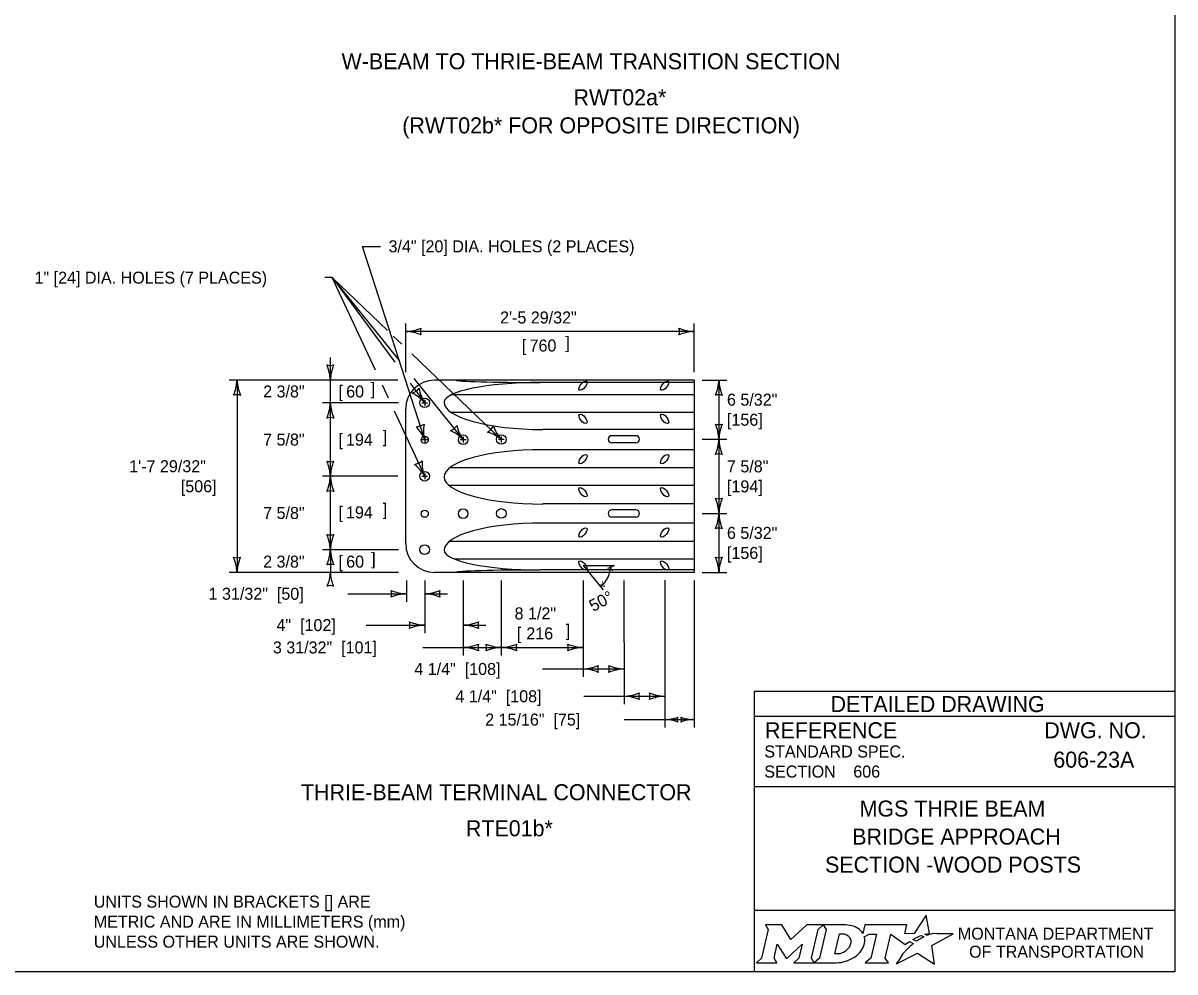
# Model space of a CAD drawing. Extents: x 49991 to 50160, y 49948 to 50051.
# Drawn here: x 50011 to 50016.75, y 49987.8 to 49992.54 of the extents above; entities that cross this region are included whole.
import ezdxf

# ---------------------------------------------------------------- set-up
doc = ezdxf.new("R2010")
doc.units = 0
for name, color, linetype in [('Default', 7, 'Continuous'), ('Level 1', 7, 'Continuous'), ('Level 10', 7, 'Continuous'), ('Level 2', 7, 'Continuous'), ('Level 3', 7, 'Continuous'), ('Level 5', 7, 'Continuous')]:
    doc.layers.add(name, color=color, linetype=linetype)

# ---------------------------------------------------------------- blocks, each defined once
blk = doc.blocks.new('ARRP')
at = {"layer": 'Level 10'}
for centre, major_axis, start_param, end_param in [((0.018, 0.564), (0, -0.565), 5.889718, 6.241987), ((-0.253, 0), (0, -0.139), 1.25906, 1.882533), ((0.023, -0.591), (0, 0.592), 0.049346, 0.385319)]:
    blk.add_ellipse(centre, major_axis=major_axis, ratio=0.77736, start_param=start_param, end_param=end_param, dxfattribs=at)
blk = doc.blocks.new('ARW')
at = {"layer": 'Default'}
for centre, radius, start, end in [((-0.1, 34.2), 34.2, 249.1967, 270.1573), ((-17.1, 0), 5.35, 335.3937, 24.6076), ((-0.1, -34.2), 34.2, 89.8431, 110.8037)]:
    blk.add_arc(centre, radius, start, end, dxfattribs=at)

msp = doc.modelspace()

# ---------------------------------------------------------------- linework, layer by layer
at = {"layer": 'Default'}
for points in [[(50015.5126, 49987.9811), (50015.5023, 49987.9867), (50015.5139, 49987.9895), (50015.5255, 49987.9915), (50015.5081, 49988.0816), (50015.4486, 49987.9903), (50015.4013, 49987.9896), (50015.4116, 49988.0337), (50015.2024, 49988.0338), (50015.1923, 49987.9913), (50015.1865, 49987.9996)], [(50014.7056, 49988.0338), (50014.7197, 49988.0104), (50014.6862, 49987.8671), (50014.6605, 49987.8446), (50014.7621, 49987.8446), (50014.7486, 49987.8674), (50014.7648, 49987.9375), (50014.8085, 49987.8685), (50014.8138, 49987.8685), (50014.8889, 49987.938), (50014.8725, 49987.8669), (50014.8478, 49987.8449), (50014.9494, 49987.8449), (50014.9356, 49987.8682), (50014.9688, 49988.0106)], [(50014.9688, 49988.0106), (50014.9941, 49988.0338), (50014.9117, 49988.0338), (50014.8321, 49987.9608), (50014.7876, 49988.0335), (50014.7056, 49988.0338)], [(50015.1077, 49988.0338), (50014.9941, 49988.0338), (50015.0088, 49988.0109), (50014.9749, 49987.8671), (50014.9494, 49987.8449), (50015.06, 49987.8449)], [(50015.1317, 49987.9471), (50015.1305, 49987.939), (50015.1273, 49987.9297), (50015.1231, 49987.9215), (50015.1175, 49987.914), (50015.111, 49987.9071), (50015.1031, 49987.9008), (50015.0948, 49987.8961), (50015.0857, 49987.8922), (50015.0766, 49987.8899), (50015.0674, 49987.889), (50015.0515, 49987.889), (50015.0751, 49987.989), (50015.0911, 49987.989), (50015.0987, 49987.9884), (50015.1063, 49987.9865), (50015.1129, 49987.9835), (50015.119, 49987.9793), (50015.1238, 49987.9743), (50015.1275, 49987.9683), (50015.1302, 49987.9621), (50015.1318, 49987.9547), (50015.1318, 49987.9517), (50015.1317, 49987.9471)], [(50015.1991, 49987.9747), (50015.2237, 49987.9878), (50015.2606, 49987.9878), (50015.232, 49987.8673), (50015.2045, 49987.8446), (50015.3207, 49987.8446), (50015.3037, 49987.8675), (50015.3319, 49987.9877), (50015.4032, 49987.936), (50015.4243, 49987.9511), (50015.444, 49987.9402)], [(50015.3882, 49987.8843), (50015.3729, 49987.8599), (50015.3682, 49987.8524), (50015.3624, 49987.8438), (50015.3601, 49987.8395), (50015.4654, 49987.8926), (50015.5493, 49987.8375), (50015.5362, 49987.9302), (50015.6431, 49987.9886), (50015.5938, 49987.9894), (50015.5637, 49987.9898), (50015.5429, 49987.9901), (50015.5361, 49987.9886), (50015.5312, 49987.9874), (50015.5228, 49987.9851), (50015.5126, 49987.9811)], [(50015.4622, 49987.9535), (50015.4598, 49987.9518), (50015.4415, 49987.9614), (50015.4518, 49987.9671), (50015.4559, 49987.9693), (50015.4645, 49987.9733), (50015.4702, 49987.9759), (50015.4781, 49987.9789), (50015.4854, 49987.9816), (50015.4972, 49987.9742), (50015.4932, 49987.9721), (50015.4886, 49987.9696), (50015.4844, 49987.9674), (50015.4794, 49987.9645), (50015.4775, 49987.9634), (50015.4748, 49987.9618), (50015.4723, 49987.9604), (50015.47, 49987.9588), (50015.4674, 49987.957), (50015.4647, 49987.9552), (50015.4622, 49987.9535)], [(50015.4021, 49987.9004), (50015.4021, 49987.9004)], [(50015.1057, 49987.8522), (50015.1141, 49987.8548), (50015.1271, 49987.8602), (50015.1475, 49987.8712)]]:
    msp.add_lwpolyline(points, dxfattribs=at)
for centre, radius, start, end in [((50015.1308, 49987.9554), 0.0709, 339.53292, 15.85821), ((50015.0868, 49987.9727), 0.1183, 300.91025, 339.13831)]:
    msp.add_arc(centre, radius, start, end, dxfattribs=at)
for centre, major_axis, ratio, start_param, end_param in [((50015.1056, 49987.9864), (0.0834, -0.0037), 0.568097, 0.61298, 1.570796), ((50015.1612, 49987.9937), (0.0361, -0.0295), 0.469099, 1.225588, 1.570796), ((50015.4329, 49987.9305), (-0.0112, -0.0097), 0.021651, 3.157348, 6.283185), ((50015.3952, 49987.8923), (-0.00694, -0.00806), 0.008222, 0, 3.137361), ((50015.4119, 49987.9106), (-0.0098, -0.0102), 0.016458, 3.141593, 6.279097), ((50015.0603, 49987.9932), (0, 0.1484), 0.987302, 3.139398, 3.456847)]:
    msp.add_ellipse(centre, major_axis=major_axis, ratio=ratio, start_param=start_param, end_param=end_param, dxfattribs=at)
at = {"layer": 'Level 1'}
for p, q in [((50014.3502, 49990.7535), (50013.0542, 49990.7535)), ((50014.3502, 49990.7415), (50013.5821, 49990.7415)), ((50014.3502, 49990.7535), (50014.3502, 49989.7935)), ((50014.3502, 49990.6797), (50013.1373, 49990.6797)), ((50012.9102, 49989.9381), (50012.9102, 49990.6095)), ((50014.3502, 49990.5915), (50013.1384, 49990.5915)), ((50014.3502, 49990.5076), (50013.5941, 49990.5076)), ((50014.0593, 49990.4761), (50013.9393, 49990.4761)), ((50014.0593, 49990.4401), (50013.9393, 49990.4401)), ((50014.3502, 49990.4061), (50013.5941, 49990.4061)), ((50014.3502, 49990.3148), (50013.1291, 49990.3148)), ((50014.3502, 49990.2266), (50013.1283, 49990.2266)), ((50014.3502, 49990.1353), (50013.5941, 49990.1353)), ((50014.0593, 49990.1057), (50013.9393, 49990.1057)), ((50014.0593, 49990.0697), (50013.9393, 49990.0697)), ((50014.3502, 49990.0401), (50013.5941, 49990.0401)), ((50014.3502, 49989.9485), (50013.1287, 49989.9485)), ((50014.3502, 49989.8602), (50013.1529, 49989.8602)), ((50014.3502, 49989.7935), (50013.0542, 49989.7935)), ((50014.3502, 49989.8055), (50013.5821, 49989.8055))]:
    msp.add_line(p, q, dxfattribs=at)
msp.add_lwpolyline([(49999.3835, 49998.9992), (50016.7501, 49998.9992), (50016.7501, 49987.7988), (49999.3835, 49987.7988)], close=True, dxfattribs=at)
for centre, radius in [((50013.0049, 49990.64), 0.024), ((50013.0049, 49990.4557), 0.018), ((50013.197, 49990.4557), 0.024), ((50013.3875, 49990.4569), 0.024), ((50013.0049, 49990.2735), 0.024), ((50013.0049, 49990.0866), 0.018), ((50013.197, 49990.0866), 0.024), ((50013.3875, 49990.0877), 0.024), ((50013.0049, 49989.9069), 0.024)]:
    msp.add_circle(centre, radius, dxfattribs=at)
for centre, radius, start, end in [((50013.0542, 49990.6095), 0.144, 90, 180), ((50013.9393, 49990.4581), 0.018, 90, 270), ((50014.0593, 49990.4581), 0.018, 270, 90), ((50013.9393, 49990.0877), 0.018, 90, 270), ((50014.0593, 49990.0877), 0.018, 270, 90), ((50013.0542, 49989.9375), 0.144, 180, 270)]:
    msp.add_arc(centre, radius, start, end, dxfattribs=at)
for centre, major_axis, ratio, start_param, end_param in [((50013.5821, 49990.6425), (-0.48, 0), 0.2062, 4.712389, 6.283185), ((50013.5821, 49990.7535), (-0.4208, 0), 0.028516, 0, 1.570796), ((50013.5941, 49990.6425), (-0.492, 0), 0.27561, 0, 1.570796), ((50013.5941, 49990.2705), (-0.492, 0), 0.27561, 4.712389, 6.283185), ((50013.5941, 49990.2702), (-0.492, 0), 0.27561, 0, 1.570796), ((50013.5941, 49989.9045), (-0.492, 0), 0.27561, 4.712389, 6.283185), ((50013.5821, 49989.9045), (-0.48, 0), 0.2062, 0, 1.570796), ((50013.5821, 49989.7935), (-0.4208, 0), 0.028516, 4.712389, 6.283185)]:
    msp.add_ellipse(centre, major_axis=major_axis, ratio=ratio, start_param=start_param, end_param=end_param, dxfattribs=at)
for centre, major_axis in [((50013.7953, 49990.7257), (-0.0182, -0.0217)), ((50014.2029, 49990.7257), (-0.0182, -0.0217)), ((50013.7953, 49990.56), (-0.0182, 0.0217)), ((50014.2029, 49990.56), (-0.0182, 0.0217)), ((50013.7953, 49990.359), (-0.0182, -0.0217)), ((50014.2029, 49990.359), (-0.0182, -0.0217)), ((50013.7953, 49990.1934), (-0.0182, 0.0217)), ((50014.2029, 49990.1934), (-0.0182, 0.0217)), ((50013.7953, 49989.993), (-0.0182, -0.0217)), ((50014.2029, 49989.993), (-0.0182, -0.0217)), ((50013.7953, 49989.8274), (-0.0182, 0.0217)), ((50014.2029, 49989.8274), (-0.0182, 0.0217))]:
    msp.add_ellipse(centre, major_axis=major_axis, ratio=0.447911, dxfattribs=at)
at = {"layer": 'Level 3'}
for p, q in [((50013.0049, 49990.4557), (50012.6945, 49991.4213)), ((50012.6945, 49991.4213), (50012.7844, 49991.4213)), ((50012.5439, 49991.2649), (50012.5063, 49991.2649)), ((50012.7588, 49990.8028), (50012.5439, 49991.2649)), ((50012.5439, 49991.2649), (50012.8551, 49990.843)), ((50012.5439, 49991.2649), (50012.8777, 49990.8514)), ((50012.5439, 49991.2649), (50012.8201, 49991.0003)), ((50012.9102, 49990.7935), (50012.9102, 49991.0361)), ((50014.3502, 49990.9961), (50012.9102, 49990.9961)), ((50014.3502, 49990.7935), (50014.3502, 49991.0361)), ((50012.848, 49990.9736), (50012.8907, 49990.9328)), ((50012.9406, 49990.885), (50013.3875, 49990.4569)), ((50012.8777, 49990.8514), (50012.8779, 49990.8511)), ((50012.8993, 49990.7831), (50012.8998, 49990.7824)), ((50012.9503, 49990.7615), (50013.197, 49990.4557)), ((50012.8702, 49990.7535), (50012.0281, 49990.7535)), ((50012.0681, 49990.7535), (50012.0681, 49989.7935)), ((50012.534, 49990.64), (50012.534, 49990.7535)), ((50012.8238, 49990.6629), (50012.7936, 49990.7278)), ((50012.9329, 49990.7376), (50013.0049, 49990.64)), ((50014.3902, 49990.7535), (50014.5138, 49990.7535)), ((50014.4738, 49990.7535), (50014.4738, 49990.4581)), ((50013.0049, 49990.6544), (50013.0049, 49990.6256)), ((50012.8735, 49990.64), (50012.494, 49990.64)), ((50012.534, 49990.2735), (50012.534, 49990.64)), ((50013.0049, 49990.2735), (50012.8538, 49990.5983)), ((50012.9905, 49990.64), (50013.0193, 49990.64)), ((50013.0049, 49990.4701), (50013.0049, 49990.4413)), ((50013.197, 49990.4701), (50013.197, 49990.4413)), ((50013.3875, 49990.4713), (50013.3875, 49990.4425)), ((50012.9905, 49990.4569), (50013.0193, 49990.4569)), ((50013.1826, 49990.4569), (50013.2114, 49990.4569)), ((50013.3731, 49990.458), (50013.4019, 49990.458)), ((50014.3902, 49990.4581), (50014.5138, 49990.4581)), ((50014.4738, 49990.4581), (50014.4738, 49990.0877)), ((50012.8702, 49990.2735), (50012.494, 49990.2735)), ((50012.534, 49989.9069), (50012.534, 49990.2735)), ((50012.9905, 49990.2735), (50013.0193, 49990.2735)), ((50013.0049, 49990.2879), (50013.0049, 49990.2591)), ((50014.3902, 49990.0877), (50014.5138, 49990.0877)), ((50014.4738, 49990.0877), (50014.4738, 49989.7935)), ((50012.8735, 49989.9069), (50012.494, 49989.9069)), ((50012.534, 49989.9069), (50012.534, 49989.7935)), ((50012.8735, 49989.7935), (50012.0281, 49989.7935)), ((50013.7953, 49989.8274), (50013.8961, 49989.7072)), ((50013.7953, 49989.8274), (50013.9521, 49989.8274)), ((50014.3902, 49989.7935), (50014.5138, 49989.7935)), ((50012.9135, 49989.7535), (50012.9135, 49989.6469)), ((50013.0049, 49989.7535), (50013.0049, 49989.4905)), ((50013.197, 49989.7535), (50013.197, 49989.3788)), ((50013.3875, 49989.7535), (50013.3875, 49989.3788)), ((50013.7953, 49989.7535), (50013.7953, 49989.2714)), ((50013.9993, 49989.7535), (50014, 49989.1352)), ((50014.2029, 49989.754), (50014.2029, 49989.0187)), ((50014.3502, 49989.7535), (50014.3502, 49989.0187)), ((50012.6207, 49989.6869), (50012.9135, 49989.6869)), ((50012.7121, 49989.5305), (50013.0049, 49989.5305)), ((50012.9954, 49989.4188), (50013.3875, 49989.4188)), ((50013.3875, 49989.4188), (50013.7953, 49989.4188)), ((50013.5937, 49989.3114), (50013.9993, 49989.3114)), ((50013.7987, 49989.1752), (50014.204, 49989.1752)), ((50014.0013, 49989.0587), (50014.3502, 49989.0587))]:
    msp.add_line(p, q, dxfattribs=at)
for points in [[(50012.534, 49990.7535), (50012.534, 49990.827), (50012.534, 49990.867)], [(50013.0049, 49989.6869), (50013.0783, 49989.6869), (50013.1183, 49989.6869)], [(50013.197, 49989.5305), (50013.2705, 49989.5305), (50013.3105, 49989.5305)]]:
    msp.add_lwpolyline(points, dxfattribs=at)
for centre, radius, start, end in [((50012.8987, 49991.2288), 0.233, 272.82731, 292.07716), ((50012.901, 49990.774), 0.2223, 67.45601, 87.63952), ((50013.0384, 49990.9961), 0.0548, 162.13882, 197.86118), ((50014.3593, 49991.2183), 0.2223, 247.45601, 267.63952), ((50014.222, 49990.9961), 0.0548, 342.13882, 17.86118), ((50014.3617, 49990.7634), 0.233, 92.82731, 112.07716), ((50012.534, 49990.8817), 0.0548, 252.13882, 287.86118), ((50012.3013, 49990.742), 0.233, 2.82731, 22.07716), ((50012.7561, 49990.7444), 0.2223, 157.45601, 177.63952), ((50011.8459, 49990.7627), 0.2223, 337.45601, 357.63952), ((50012.3008, 49990.765), 0.233, 182.82731, 202.07716), ((50014.2516, 49990.7627), 0.2223, 337.45601, 357.63952), ((50014.7065, 49990.765), 0.233, 182.82731, 202.07716), ((50012.0681, 49990.6253), 0.0548, 72.13882, 107.86118), ((50014.4738, 49990.6253), 0.0548, 72.13882, 107.86118), ((50012.3118, 49990.6492), 0.2223, 337.45601, 357.63952), ((50012.7667, 49990.6515), 0.233, 182.82731, 202.07716), ((50012.534, 49990.5118), 0.0548, 72.13882, 107.86118), ((50014.4738, 49990.5863), 0.0548, 252.13882, 287.86118), ((50014.2411, 49990.4466), 0.233, 2.82731, 22.07716), ((50014.6959, 49990.449), 0.2223, 157.45601, 177.63952), ((50014.2516, 49990.4673), 0.2223, 337.45601, 357.63952), ((50014.7065, 49990.4696), 0.233, 182.82731, 202.07716), ((50014.4738, 49990.3299), 0.0548, 72.13882, 107.86118), ((50012.534, 49990.4017), 0.0548, 252.13882, 287.86118), ((50012.3013, 49990.262), 0.233, 2.82731, 22.07716), ((50012.7561, 49990.2643), 0.2223, 157.45601, 177.63952), ((50012.3118, 49990.2826), 0.2223, 337.45601, 357.63952), ((50012.7667, 49990.285), 0.233, 182.82731, 202.07716), ((50012.534, 49990.1452), 0.0548, 72.13882, 107.86118), ((50014.4738, 49990.2159), 0.0548, 252.13882, 287.86118), ((50014.2411, 49990.0762), 0.233, 2.82731, 22.07716), ((50014.6959, 49990.0786), 0.2223, 157.45601, 177.63952), ((50014.2516, 49990.0969), 0.2223, 337.45601, 357.63952), ((50014.7065, 49990.0992), 0.233, 182.82731, 202.07716), ((50014.4738, 49989.9595), 0.0548, 72.13882, 107.86118), ((50012.534, 49990.0351), 0.0548, 252.13882, 287.86118), ((50012.3013, 49989.8954), 0.233, 2.82731, 22.07716), ((50012.7561, 49989.8977), 0.2223, 157.45601, 177.63952), ((50012.3118, 49989.9161), 0.2223, 337.45601, 357.63952), ((50012.7667, 49989.9184), 0.233, 182.82731, 202.07716), ((50012.0681, 49989.9217), 0.0548, 252.13882, 287.86118), ((50011.8353, 49989.782), 0.233, 2.82731, 22.07716), ((50012.2902, 49989.7844), 0.2223, 157.45601, 177.63952), ((50014.4738, 49989.9217), 0.0548, 252.13882, 287.86118), ((50014.2411, 49989.782), 0.233, 2.82731, 22.07716), ((50014.6959, 49989.7844), 0.2223, 157.45601, 177.63952), ((50012.534, 49989.7787), 0.0548, 72.13882, 107.86118), ((50012.334, 49989.8018), 0.2001, 337.45601, 357.63952), ((50012.7434, 49989.8039), 0.2097, 182.82731, 202.07716), ((50013.7953, 49989.8274), 0.1376, 310, 360), ((50012.534, 49989.6781), 0.0493, 72.13882, 107.86118), ((50012.9226, 49989.9091), 0.2223, 247.45601, 267.63952), ((50012.7853, 49989.6869), 0.0548, 342.13882, 17.86118), ((50012.925, 49989.4542), 0.233, 92.82731, 112.07716), ((50012.9934, 49989.9197), 0.233, 272.82731, 292.07716), ((50012.9957, 49989.4648), 0.2223, 67.45601, 87.63952), ((50013.1331, 49989.6869), 0.0548, 162.13882, 197.86118), ((50013.014, 49989.7526), 0.2223, 247.45601, 267.63952), ((50012.8766, 49989.5305), 0.0548, 342.13882, 17.86118), ((50013.0164, 49989.2977), 0.233, 92.82731, 112.07716), ((50013.1855, 49989.7632), 0.233, 272.82731, 292.07716), ((50013.1879, 49989.3083), 0.2223, 67.45601, 87.63952), ((50013.3252, 49989.5305), 0.0548, 162.13882, 197.86118), ((50013.1855, 49989.6515), 0.233, 272.82731, 292.07716), ((50013.3252, 49989.4188), 0.0548, 162.13882, 197.86118), ((50013.3967, 49989.641), 0.2223, 247.45601, 267.63952), ((50013.2593, 49989.4188), 0.0548, 342.13882, 17.86118), ((50013.376, 49989.6515), 0.233, 272.82731, 292.07716), ((50013.5157, 49989.4188), 0.0548, 162.13882, 197.86118), ((50013.8045, 49989.641), 0.2223, 247.45601, 267.63952), ((50013.6671, 49989.4188), 0.0548, 342.13882, 17.86118), ((50013.1879, 49989.1967), 0.2223, 67.45601, 87.63952), ((50013.399, 49989.1861), 0.233, 92.82731, 112.07716), ((50013.3784, 49989.1967), 0.2223, 67.45601, 87.63952), ((50013.8068, 49989.1861), 0.233, 92.82731, 112.07716), ((50013.7838, 49989.5441), 0.233, 272.82731, 292.07716), ((50013.9235, 49989.3114), 0.0548, 162.13882, 197.86118), ((50014.0089, 49989.5336), 0.2223, 247.45601, 267.63952), ((50013.8716, 49989.3114), 0.0548, 342.13882, 17.86118), ((50013.7862, 49989.0893), 0.2223, 67.45601, 87.63952), ((50014.0113, 49989.0787), 0.233, 92.82731, 112.07716), ((50013.9884, 49989.408), 0.233, 272.82731, 292.07716), ((50013.9908, 49988.9531), 0.2223, 67.45601, 87.63952), ((50014.1281, 49989.1752), 0.0548, 162.13882, 197.86118), ((50014.2121, 49989.3974), 0.2223, 247.45601, 267.63952), ((50014.0747, 49989.1752), 0.0548, 342.13882, 17.86118), ((50014.2144, 49988.9425), 0.233, 92.82731, 112.07716)]:
    msp.add_arc(centre, radius, start, end, dxfattribs=at)
at = {"layer": 'Level 5'}
for p, q in [((50016.7501, 49989.1988), (50014.6501, 49989.1988)), ((50014.6501, 49989.1988), (50014.6501, 49987.7988)), ((50016.7501, 49989.0738), (50014.6501, 49989.0738)), ((50016.3862, 49988.8587), (50016.3862, 49988.8587)), ((50015.1444, 49988.7993), (50015.1444, 49988.7993)), ((50016.7501, 49988.7238), (50014.6501, 49988.7238)), ((50015.7001, 49988.4747), (50015.7001, 49988.4747)), ((50016.7501, 49988.1057), (50014.6501, 49988.1057))]:
    msp.add_line(p, q, dxfattribs=at)

# ---------------------------------------------------------------- block references
at = {"layer": 'Level 3'}
for name, p, xscale, yscale, rotation in [('ARRP', (50013.0049, 49990.64), 0.5000000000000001, 0.5, -53.585703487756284), ('ARRP', (50013.0049, 49990.4557), 0.5000000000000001, 0.5, -72.17893826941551), ('ARRP', (50013.0049, 49990.4557), 0.5000000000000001, 0.5, -72.17893826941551), ('ARRP', (50013.197, 49990.4557), 0.5000000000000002, 0.4999999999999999, -51.093024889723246), ('ARRP', (50013.197, 49990.4557), 0.5000000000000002, 0.4999999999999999, -51.093024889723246), ('ARRP', (50013.3875, 49990.4569), 0.5, 0.5, -43.76640499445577), ('ARRP', (50013.3875, 49990.4569), 0.5, 0.5, -43.76640499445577), ('ARRP', (50013.0049, 49990.2735), 0.5000000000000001, 0.5, -65.06566668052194), ('ARRP', (50013.0049, 49990.2735), 0.5000000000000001, 0.5, -65.06566668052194), ('ARW', (50014.2019, 49989.0587), 0.0054, 0.0054, 180)]:
    msp.add_blockref(name, p, dxfattribs=dict(at, xscale=xscale, yscale=yscale, rotation=rotation))
at = {"layer": 'Level 3', "xscale": 0.0054, "yscale": 0.0054}
msp.add_blockref('ARW', (50014.3502, 49989.0587), dxfattribs=at)

# ---------------------------------------------------------------- texts
at = {"layer": 'Default'}
for s, p in [('MONTANA DEPARTMENT', (50015.6663, 49987.96)), ('OF TRANSPORTATION', (50015.7225, 49987.87))]:
    msp.add_text(s, height=0.06, dxfattribs=at).set_placement(p)
at = {"layer": 'Level 2'}
for s, height, p in [('W-BEAM TO THRIE-BEAM TRANSITION SECTION', 0.08, (50012.5898, 49992.3053)), ('RWT02a*', 0.08, (50013.7476, 49992.1253)), ('(RWT02b* FOR OPPOSITE DIRECTION)', 0.08, (50012.8929, 49991.9853)), ('2\'-5 29/32"', 0.06, (50013.3811, 49991.0361)), ('[', 0.06, (50013.4895, 49990.8961)), ('760', 0.06, (50013.5285, 49990.8961)), ('2 3/8"', 0.06, (50012.1986, 49990.6668)), ('[', 0.06, (50012.574, 49990.6668)), ('60', 0.06, (50012.613, 49990.6667)), ('6 5/32"', 0.06, (50014.5138, 49990.6258)), ('[156]', 0.06, (50014.5138, 49990.5258)), ('7 5/8"', 0.06, (50012.1986, 49990.4267)), ('[', 0.06, (50012.574, 49990.4267)), ('194', 0.06, (50012.6121, 49990.4267)), ('1\'-7 29/32"', 0.06, (50011.5299, 49990.2935)), ('7 5/8"', 0.06, (50014.5138, 49990.2929)), ('[506]', 0.06, (50011.7876, 49990.1935)), ('[194]', 0.06, (50014.5138, 49990.1929)), ('[', 0.06, (50012.574, 49990.0631)), ('194', 0.06, (50012.6121, 49990.0631)), ('7 5/8"', 0.06, (50012.1986, 49990.0602)), ('6 5/32"', 0.06, (50014.5138, 49989.9606)), ('[156]', 0.06, (50014.5138, 49989.8606)), ('2 3/8"', 0.06, (50012.1986, 49989.8173)), ('[', 0.06, (50012.574, 49989.8173)), ('60', 0.06, (50012.613, 49989.8173)), ('1 31/32"  [50]', 0.06, (50011.9263, 49989.6569)), ('8 1/2"', 0.06, (50013.4536, 49989.5588)), ('4"  [102]', 0.06, (50012.2651, 49989.5005)), ('[', 0.06, (50013.4643, 49989.4588)), ('216', 0.06, (50013.5123, 49989.4588)), ('3 31/32"  [101]', 0.06, (50012.2472, 49989.3888)), ('4 1/4"  [108]', 0.06, (50012.9533, 49989.2814)), ('4 1/4"  [108]', 0.06, (50013.1582, 49989.1452)), ('2 15/16"  [75]', 0.06, (50013.307, 49989.0287)), ('606-23A', 0.08, (50016.1428, 49988.8187)), ('606', 0.06, (50015.1444, 49988.7693)), ('THRIE-BEAM TERMINAL CONNECTOR', 0.08, (50012.3874, 49988.6561)), ('MGS THRIE BEAM', 0.08, (50015.1757, 49988.5746)), ('RTE01b*', 0.08, (50013.2106, 49988.4761)), (' BRIDGE APPROACH', 0.08, (50015.1094, 49988.4347)), ('SECTION -WOOD POSTS', 0.08, (50015.0034, 49988.2947)), ('UNITS SHOWN IN BRACKETS [] ARE ', 0.06, (50011.3531, 49988.12)), ('METRIC AND ARE IN MILLIMETERS (mm) ', 0.06, (50011.3531, 49988.02)), ('UNLESS OTHER UNITS ARE SHOWN.', 0.06, (50011.3531, 49987.92))]:
    msp.add_text(s, height=height, dxfattribs=at).set_placement(p)
for s, rotation, p in [('3/4" [20] DIA. HOLES (2 PLACES)', 360, (50012.8244, 49991.3913)), ('1" [24] DIA. HOLES (7 PLACES)', 360, (50011.0573, 49991.2349)), ('[', 180, (50013.7292, 49990.9562)), ('[', 180, (50012.757, 49990.726)), ('[', 180, (50012.8179, 49990.4867)), ('[', 180, (50012.8179, 49990.1231)), ('[', 180, (50012.7602, 49989.8773)), ('50°', 28.00927, (50013.8458, 49989.5951)), ('[', 180, (50013.7317, 49989.5188))]:
    msp.add_text(s, height=0.06, rotation=rotation, dxfattribs=at).set_placement(p)
at = {"layer": 'Level 3'}
for rotation, p in [(83.99364, (50013.9445, 49989.7992)), (226.00636, (50013.892, 49989.7512))]:
    msp.add_text('A', height=0.0288, rotation=rotation, dxfattribs=at).set_placement(p)
at = {"layer": 'Level 5'}
for s, height, p in [('DETAILED DRAWING', 0.0799, (50015.0311, 49989.0963)), ('REFERENCE', 0.08, (50014.7037, 49988.9654)), ('DWG. NO.', 0.08, (50016.0979, 49988.9654)), ('STANDARD SPEC.', 0.06, (50014.7004, 49988.8694)), ('SECTION', 0.06, (50014.7004, 49988.7694))]:
    msp.add_text(s, height=height, dxfattribs=at).set_placement(p)

doc.saveas('drawing.dxf')
